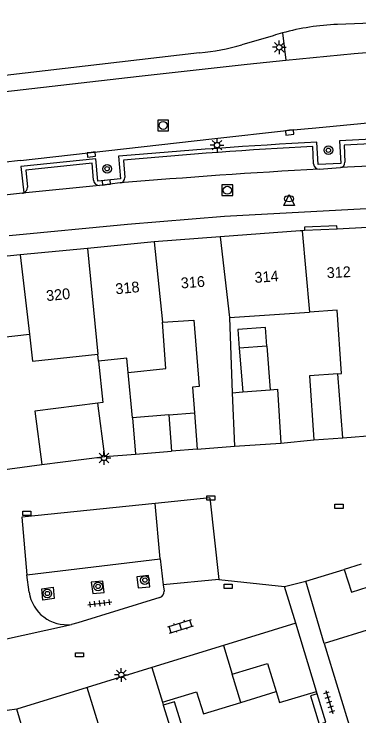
# Model space of a CAD drawing. Extents: x 132999 to 136000, y 398499 to 400501.
# Drawn here: x 133325.8 to 133357.7, y 398595 to 398660.1 of the extents above; entities that cross this region are included whole.
import ezdxf

# ---------------------------------------------------------------- set-up
doc = ezdxf.new("R2010")
doc.units = 0
for name, color, linetype in [('gg-afsc-erfafscheiding', 7, 'Continuous'), ('gg-afsc-muur', 7, 'Continuous'), ('gg-anno-huisnummerreeks BGT', 7, 'Continuous'), ('gg-bbg-bijgebouw', 7, 'Continuous'), ('gg-bbg-gedigitaliseerde bebouwing', 7, 'Continuous'), ('gg-bbg-gedigitaliseerde bijgebouw', 7, 'Continuous'), ('gg-bbg-hoofdgebouw', 7, 'Continuous'), ('gg-bbg-luifel en loopbrug', 7, 'Continuous'), ('gg-bbg-tussenscheiding', 7, 'Continuous'), ('gg-knt-verharding', 7, 'Continuous'), ('gg-knt-verharding nz', 7, 'Continuous'), ('gt-grn-groengrens', 7, 'Continuous'), ('gt-grn-weggrens', 7, 'Continuous'), ('gt-symb-boom', 7, 'Continuous'), ('gt-symb-brandkraan', 7, 'Continuous'), ('gt-symb-klinker verharding', 7, 'Continuous'), ('gt-symb-kolk', 7, 'Continuous'), ('gt-symb-kolk center center', 7, 'Continuous'), ('gt-symb-lichtmast', 7, 'Continuous'), ('gt-symb-rioolschacht', 7, 'Continuous'), ('gt-symb-tegel verharding', 7, 'Continuous'), ('gt-symb-waterafsluiter', 7, 'Continuous')]:
    doc.layers.add(name, color=color, linetype=linetype)

# ---------------------------------------------------------------- blocks, each defined once
blk = doc.blocks.new('gt0-BOOM')
at = {"layer": 'gt-symb-boom'}
for radius in [0.4, 0.2]:
    blk.add_circle((0, 0), radius, dxfattribs=at)
blk = doc.blocks.new('gt0-LMAST')
at = {"layer": 'gt-symb-lichtmast'}
for p, q in [((-0.182, 0.173), (-0.447, 0.438)), ((-0.005, 0.246), (-0.005, 0.621)), ((0.172, 0.173), (0.437, 0.438)), ((-0.255, -0.004), (-0.63, -0.004)), ((-0.182, -0.181), (-0.447, -0.446)), ((-0.005, -0.254), (-0.005, -0.629)), ((0.437, -0.446), (0.172, -0.181)), ((0.245, -0.004), (0.62, -0.004))]:
    blk.add_line(p, q, dxfattribs=at)
blk.add_circle((-0.005, -0.004), 0.25, dxfattribs=at)
blk = doc.blocks.new('gt0-KOLK')
at = {"layer": 'gt-symb-kolk'}
blk.add_lwpolyline([(0, 0), (0.375, 0), (0.375, 0.4), (-0.375, 0.4), (-0.375, 0), (0, 0)], dxfattribs=at)
blk = doc.blocks.new('gt0-RS')
at = {"layer": 'gt-symb-rioolschacht'}
blk.add_lwpolyline([(-0.5, -0.5), (0.5, -0.5), (0.5, 0.5), (-0.5, 0.5)], close=True, dxfattribs=at)
blk.add_circle((0, 0), 0.375, dxfattribs=at)
blk = doc.blocks.new('gt0-WAFSL')
at = {"layer": 'gt-symb-waterafsluiter'}
for p, q in [((-0.5, -0.333), (0, 0.667)), ((0, 0.667), (0.5, -0.333)), ((0.5, -0.333), (-0.5, -0.333))]:
    blk.add_line(p, q, dxfattribs=at)
blk = doc.blocks.new('gt0-BR')
at = {"layer": 'gt-symb-brandkraan'}
for centre, radius, start, end in [((-0.244, 0), 0.206, 107.56694, 252.43307), ((0.599, -2.664), 3, 106.89205, 107.56694), ((0, -0.691), 0.938, 73.10799, 106.89205), ((-0.599, -2.664), 3, 72.43309, 73.10799), ((0.244, 0), 0.206, 287.56695, 72.43309), ((0.599, 2.664), 3, 252.43307, 253.10797), ((0, 0.691), 0.938, 253.10797, 286.89206), ((-0.599, 2.664), 3, 286.89206, 287.56695)]:
    blk.add_arc(centre, radius, start, end, dxfattribs=at)
blk = doc.blocks.new('gt0-KOLKCC')
at = {"layer": 'gt-symb-kolk center center'}
blk.add_lwpolyline([(-0.375, 0.2), (0.375, 0.2), (0.375, -0.2), (-0.375, -0.2)], close=True, dxfattribs=at)
blk = doc.blocks.new('gt0-KL1')
at = {"layer": 'gt-symb-klinker verharding'}
for p, q in [((-1.15, 0.3), (1.15, 0.3)), ((-1, -0.3), (-1, 0.3)), ((-0.5, 0.3), (-0.5, 0.45)), ((0, -0.3), (0, 0.3)), ((0.5, 0.3), (0.5, 0.45)), ((1, -0.3), (1, 0.3)), ((-1.15, -0.3), (1.15, -0.3)), ((-0.5, -0.45), (-0.5, -0.3)), ((0.5, -0.45), (0.5, -0.3))]:
    blk.add_line(p, q, dxfattribs=at)
blk = doc.blocks.new('gt0-TEG1')
at = {"layer": 'gt-symb-tegel verharding'}
for p, q in [((-1.125, 0), (1.125, 0)), ((-0.9, -0.25), (-0.9, 0.25)), ((-0.45, -0.25), (-0.45, 0.25)), ((0, -0.25), (0, 0.25)), ((0.45, -0.25), (0.45, 0.25)), ((0.9, -0.25), (0.9, 0.25))]:
    blk.add_line(p, q, dxfattribs=at)

msp = doc.modelspace()

# ---------------------------------------------------------------- linework, layer by layer
at = {"layer": 'gg-afsc-erfafscheiding'}
for p, q in [((133350.466, 398620.316), (133353.521, 398620.613)), ((133352.765, 398607.513), (133356.34, 398608.611)), ((133354.47, 398601.751), (133352.765, 398607.513))]:
    msp.add_line(p, q, dxfattribs=at)
at = {"layer": 'gg-afsc-muur'}
msp.add_line((133353.828, 398597.078), (133353.76, 398597.301), dxfattribs=at)
msp.add_lwpolyline([(133322.34, 398617.555), (133323.538, 398617.681), (133328.332, 398618.321)], dxfattribs=at)
at = {"layer": 'gg-bbg-bijgebouw'}
for p, q in [((133334.17, 398619.068), (133337.027, 398619.282)), ((133342.725, 398619.753), (133340.336, 398619.556)), ((133328.332, 398618.321), (133334.17, 398619.068)), ((133357.897, 398609.091), (133356.34, 398608.611)), ((133351.85, 398603.621), (133345.16, 398601.562)), ((133353.76, 398597.301), (133351.85, 398603.621)), ((133345.16, 398601.562), (133338.521, 398599.519)), ((133338.521, 398599.519), (133332.549, 398597.68)), ((133332.549, 398597.68), (133326.02, 398595.671)), ((133326.02, 398595.671), (133320.211, 398594.881))]:
    msp.add_line(p, q, dxfattribs=at)
msp.add_lwpolyline([(133356.34, 398608.611), (133356.99, 398606.511), (133358.545, 398606.989)], dxfattribs=at)
at = {"layer": 'gg-bbg-gedigitaliseerde bebouwing'}
for p, q in [((133345.699, 398631.937), (133353.103, 398632.445)), ((133345.699, 398631.937), (133345.965, 398624.984)), ((133333.602, 398627.913), (133333.536, 398628.558)), ((133356.19, 398620.811), (133355.74, 398626.725)), ((133345.965, 398624.984), (133346.17, 398620.038))]:
    msp.add_line(p, q, dxfattribs=at)
for points in [[(133355.74, 398626.725), (133356.068, 398626.749), (133355.688, 398632.623), (133353.103, 398632.445)], [(133336.331, 398626.856), (133339.813, 398627.211), (133339.521, 398631.512)], [(133339.521, 398631.512), (133342.414, 398631.711), (133342.895, 398625.546), (133342.277, 398625.498), (133342.463, 398623.111)], [(133324.421, 398623.146), (133323.901, 398626.912), (133324.611, 398627.01), (133324.188, 398630.078), (133327.196, 398630.411)], [(133327.196, 398630.411), (133327.488, 398627.89), (133333.536, 398628.558)]]:
    msp.add_lwpolyline(points, dxfattribs=at)
at = {"layer": 'gg-bbg-gedigitaliseerde bijgebouw'}
for p, q in [((133349.177, 398629.291), (133346.623, 398629.116)), ((133346.623, 398629.116), (133346.936, 398625.059)), ((133349.177, 398629.291), (133349.488, 398625.256)), ((133336.747, 398622.665), (133336.331, 398626.856)), ((133346.936, 398625.059), (133349.488, 398625.256)), ((133340.106, 398622.927), (133342.463, 398623.111)), ((133336.747, 398622.665), (133337.027, 398619.282)), ((133340.106, 398622.927), (133340.336, 398619.556)), ((133346.777, 398596.294), (133345.974, 398598.911)), ((133339.508, 398596.302), (133339.589, 398596.039)), ((133339.589, 398596.039), (133340.446, 398593.25))]:
    msp.add_line(p, q, dxfattribs=at)
for points in [[(133333.602, 398627.913), (133333.982, 398624.085), (133333.535, 398624.028)], [(133333.535, 398624.028), (133327.697, 398623.281), (133328.332, 398618.321)], [(133345.974, 398598.911), (133349.218, 398599.908), (133350.022, 398597.292)], [(133339.508, 398596.302), (133342.668, 398597.274), (133343.298, 398595.225), (133346.777, 398596.294)], [(133350.022, 398597.292), (133350.336, 398596.272), (133353.76, 398597.301)]]:
    msp.add_lwpolyline(points, dxfattribs=at)
at = {"layer": 'gg-bbg-hoofdgebouw'}
for p, q in [((133352.667, 398639.992), (133352.454, 398639.982)), ((133355.673, 398640.139), (133352.667, 398639.992)), ((133358.488, 398640.277), (133355.673, 398640.139)), ((133344.844, 398639.418), (133338.74, 398638.961)), ((133338.74, 398638.961), (133332.558, 398638.354)), ((133332.558, 398638.354), (133326.348, 398637.743)), ((133326.348, 398637.743), (133320.32, 398637.151)), ((133356.19, 398620.811), (133359.419, 398621.051)), ((133342.725, 398619.753), (133346.17, 398620.038)), ((133367.805, 398605.851), (133354.47, 398601.751)), ((133354.47, 398601.751), (133357.49, 398591.961))]:
    msp.add_line(p, q, dxfattribs=at)
msp.add_lwpolyline([(133352.454, 398639.982), (133352.24, 398639.971), (133344.844, 398639.418)], dxfattribs=at)
at = {"layer": 'gg-bbg-luifel en loopbrug'}
for p, q in [((133345.965, 398624.984), (133346.936, 398625.059)), ((133340.106, 398622.927), (133336.747, 398622.665)), ((133353.521, 398620.613), (133356.19, 398620.811)), ((133346.17, 398620.038), (133350.466, 398620.316)), ((133337.027, 398619.282), (133340.336, 398619.556)), ((133346.777, 398596.294), (133350.022, 398597.292)), ((133354.63, 398594.458), (133353.828, 398597.078))]:
    msp.add_line(p, q, dxfattribs=at)
for points in [[(133349.177, 398629.291), (133349.045, 398631.007), (133346.491, 398630.832), (133346.623, 398629.116)], [(133355.74, 398626.725), (133353.115, 398626.53), (133353.521, 398620.613)], [(133349.488, 398625.256), (133350.143, 398625.306), (133350.466, 398620.316)], [(133353.828, 398597.078), (133353.2, 398596.889), (133354.004, 398594.264), (133354.63, 398594.458)], [(133340.446, 398593.25), (133341.488, 398593.57), (133340.631, 398596.36), (133339.589, 398596.039)]]:
    msp.add_lwpolyline(points, dxfattribs=at)
at = {"layer": 'gg-bbg-tussenscheiding'}
for p, q in [((133352.454, 398639.982), (133353.103, 398632.445)), ((133344.844, 398639.418), (133345.699, 398631.937)), ((133338.74, 398638.961), (133339.521, 398631.512)), ((133332.558, 398638.354), (133333.536, 398628.558)), ((133326.348, 398637.743), (133327.196, 398630.411)), ((133334.17, 398619.068), (133333.535, 398624.028)), ((133342.463, 398623.111), (133342.725, 398619.753)), ((133345.16, 398601.562), (133345.974, 398598.911)), ((133338.521, 398599.519), (133339.508, 398596.302)), ((133334.084, 398592.681), (133332.549, 398597.68)), ((133327.558, 398590.673), (133326.02, 398595.671))]:
    msp.add_line(p, q, dxfattribs=at)
msp.add_lwpolyline([(133336.331, 398626.856), (133336.2, 398628.178), (133333.602, 398627.913)], dxfattribs=at)
at = {"layer": 'gg-knt-verharding'}
for p, q in [((133349.744, 398658.05), (133346.859, 398657.2)), ((133353.495, 398646.174), (133353.428, 398647.779)), ((133335.902, 398646.506), (133336.037, 398644.915)), ((133374.553, 398646.75), (133355.977, 398645.83)), ((133332.99, 398646.236), (133326.857, 398645.59)), ((133333.132, 398644.656), (133332.99, 398646.236)), ((133354.023, 398645.69), (133355.977, 398645.83)), ((133326.857, 398645.59), (133327.02, 398644.013)), ((133333.693, 398644.177), (133326.562, 398643.467)), ((133335.601, 398644.41), (133333.693, 398644.177)), ((133326.562, 398643.467), (133324.906, 398643.284)), ((133326.944, 398608.104), (133339.286, 398609.597)), ((133339.286, 398609.597), (133339.581, 398607.199)), ((133327.171, 398606.507), (133326.944, 398608.104)), ((133350.799, 398607.021), (133352.765, 398607.513)), ((133339.581, 398607.199), (133339.654, 398606.609)), ((133351.85, 398603.621), (133350.799, 398607.021))]:
    msp.add_line(p, q, dxfattribs=at)
for points in [[(133453.448, 398662.925), (133412.622, 398661.315), (133381.428, 398660.103), (133355.694, 398659.091)], [(133350.927, 398655.783), (133357.236, 398656.406), (133367.187, 398657.204), (133377.178, 398657.758), (133430.066, 398659.92), (133453.448, 398660.859)], [(133342.953, 398656.457), (133323.066, 398654.162), (133314.166, 398653.15), (133302.256, 398651.632), (133295.311, 398650.674)], [(133290.532, 398648.53), (133298.68, 398649.694), (133308.598, 398651.006), (133337.358, 398654.307), (133347.341, 398655.429), (133350.927, 398655.783)], [(133353.699, 398649.52), (133360.438, 398650.166), (133370.464, 398650.895), (133380.886, 398651.413), (133391.12, 398651.88), (133412.565, 398652.717), (133432.02, 398653.487), (133479.205, 398655.389)], [(133415.393, 398651.055), (133396.943, 398650.265), (133397.027, 398648.166), (133394.946, 398648.082), (133394.855, 398650.211), (133376.431, 398649.353), (133376.529, 398647.24), (133374.436, 398647.161), (133374.324, 398649.257), (133355.883, 398648.327), (133356.009, 398646.222), (133353.912, 398646.125), (133353.788, 398648.192)], [(133326.358, 398646.495), (133344.075, 398648.503), (133351.257, 398649.286), (133353.699, 398649.52)], [(133374.02, 398647.208), (133373.959, 398648.807), (133356.318, 398647.923), (133356.388, 398646.329)], [(133325.321, 398639.532), (133336.268, 398640.603), (133345.259, 398641.339), (133373.19, 398642.858), (133394.151, 398643.82), (133414.124, 398644.679), (133475.012, 398647.182), (133479.623, 398647.374)], [(133326.358, 398646.495), (133316.542, 398645.383), (133313.336, 398645.005)], [(133335.457, 398646.88), (133335.639, 398644.789), (133333.544, 398644.574), (133333.343, 398646.643), (133326.395, 398645.945), (133326.676, 398643.5)], [(133355.673, 398640.139), (133355.658, 398640.443), (133352.652, 398640.304), (133352.667, 398639.992)], [(133332.922, 398607.42), (133333.056, 398606.381), (133334.124, 398606.486), (133333.99, 398607.525), (133332.922, 398607.42)], [(133337.133, 398607.94), (133337.263, 398606.893), (133338.338, 398607.014), (133338.208, 398608.061), (133337.133, 398607.94)], [(133328.348, 398606.806), (133329.398, 398606.959), (133329.499, 398605.907), (133328.449, 398605.754), (133328.348, 398606.806)], [(133339.273, 398606.019), (133331.69, 398603.652), (133331.106, 398603.523)]]:
    msp.add_lwpolyline(points, dxfattribs=at)
for centre, radius, start, end in [((133356.578, 398636.516), 22.592, 92.24129, 105.30527), ((133356.669, 398636.209), 22.913, 105.32296, 107.59156), ((133340.869, 398678.05), 21.693, 275.51195, 286.02833), ((133382.239, 398121.963), 526.998, 93.09475, 95.09292), ((133373.224, 398253.955), 394.322, 92.87764, 95.43112), ((133354.005, 398646.201), 0.511, 183.00781, 271.9713), ((133355.926, 398646.29), 0.463, 276.26857, 4.77846), ((133387.604, 398029.176), 617.428, 93.117795, 94.831496), ((133333.664, 398644.711), 0.534, 185.86587, 273.15058), ((133335.552, 398644.893), 0.486, 275.8143, 2.57326), ((133326.466, 398644.013), 0.554, 292.29015, 0.02099), ((133326.461, 398644.03), 0.572, 280.18805, 292.10063), ((133330.645, 398607.002), 3.509, 188.10622, 277.54604), ((133339.109, 398606.543), 0.549, 287.41081, 6.88346)]:
    msp.add_arc(centre, radius, start, end, dxfattribs=at)
at = {"layer": 'gg-knt-verharding nz'}
for p, q in [((133343.89, 398615.239), (133338.838, 398614.721)), ((133343.89, 398615.239), (133344.716, 398607.672)), ((133344.716, 398607.672), (133339.581, 398607.199))]:
    msp.add_line(p, q, dxfattribs=at)
msp.add_lwpolyline([(133338.838, 398614.721), (133326.481, 398613.454), (133326.944, 398608.104)], dxfattribs=at)
at = {"layer": 'gt-grn-groengrens'}
msp.add_line((133350.614, 398658.307), (133350.927, 398655.783), dxfattribs=at)
at = {"layer": 'gt-grn-weggrens'}
for p, q in [((133339.286, 398609.597), (133338.838, 398614.721)), ((133344.716, 398607.672), (133350.799, 398607.021)), ((133320.204, 398601.119), (133331.106, 398603.523))]:
    msp.add_line(p, q, dxfattribs=at)

# ---------------------------------------------------------------- block references
at = {"layer": 'gt-symb-boom'}
for p in [(133354.863, 398647.439), (133334.392, 398645.729), (133337.884, 398607.621), (133333.548, 398607.036), (133328.857, 398606.383)]:
    msp.add_blockref('gt0-BOOM', p, dxfattribs=at)
at = {"layer": 'gt-symb-brandkraan'}
msp.add_blockref('gt0-BR', (133351.221, 398642.951), dxfattribs=at)
at = {"layer": 'gt-symb-klinker verharding', "rotation": 17.094305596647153}
msp.add_blockref('gt0-KL1', (133341.182, 398603.335), dxfattribs=at)
at = {"layer": 'gt-symb-kolk'}
for p, rotation in [((133351.257, 398649.286), -173.78190170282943), ((133332.911, 398647.237), -173.5386116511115), ((133334.339, 398644.256), 6.989885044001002)]:
    msp.add_blockref('gt0-KOLK', p, dxfattribs=dict(at, rotation=rotation))
at = {"layer": 'gt-symb-kolk center center'}
for p in [(133343.987, 398615.238), (133355.851, 398614.466), (133326.953, 398613.804), (133345.6, 398607.05), (133331.837, 398600.701)]:
    msp.add_blockref('gt0-KOLKCC', p, dxfattribs=at)
at = {"layer": 'gt-symb-lichtmast'}
for p in [(133350.326, 398656.979), (133344.569, 398647.92), (133334.101, 398618.943), (133335.706, 398598.843)]:
    msp.add_blockref('gt0-LMAST', p, dxfattribs=at)
at = {"layer": 'gt-symb-rioolschacht'}
for p in [(133339.571, 398649.741), (133345.512, 398643.736)]:
    msp.add_blockref('gt0-RS', p, dxfattribs=at)
at = {"layer": 'gt-symb-tegel verharding'}
for p, rotation in [((133333.711, 398605.472), 7.0042592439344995), ((133354.953, 398596.332), -72.96046487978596)]:
    msp.add_blockref('gt0-TEG1', p, dxfattribs=dict(at, rotation=rotation))
at = {"layer": 'gt-symb-waterafsluiter'}
msp.add_blockref('gt0-WAFSL', (133351.232, 398642.671), dxfattribs=at)

# ---------------------------------------------------------------- texts
at = {"layer": 'gg-anno-huisnummerreeks BGT'}
for s, rotation, p in [('314', 4.3, (133348.062, 398635.145)), ('312', 2.8, (133354.734, 398635.588)), ('316', 4.3, (133341.243, 398634.635)), ('318', 5.6, (133335.204, 398634.092)), ('320', 5.6, (133328.791, 398633.461))]:
    msp.add_text(s, height=1, rotation=rotation, dxfattribs=at).set_placement(p)

doc.saveas('drawing.dxf')
